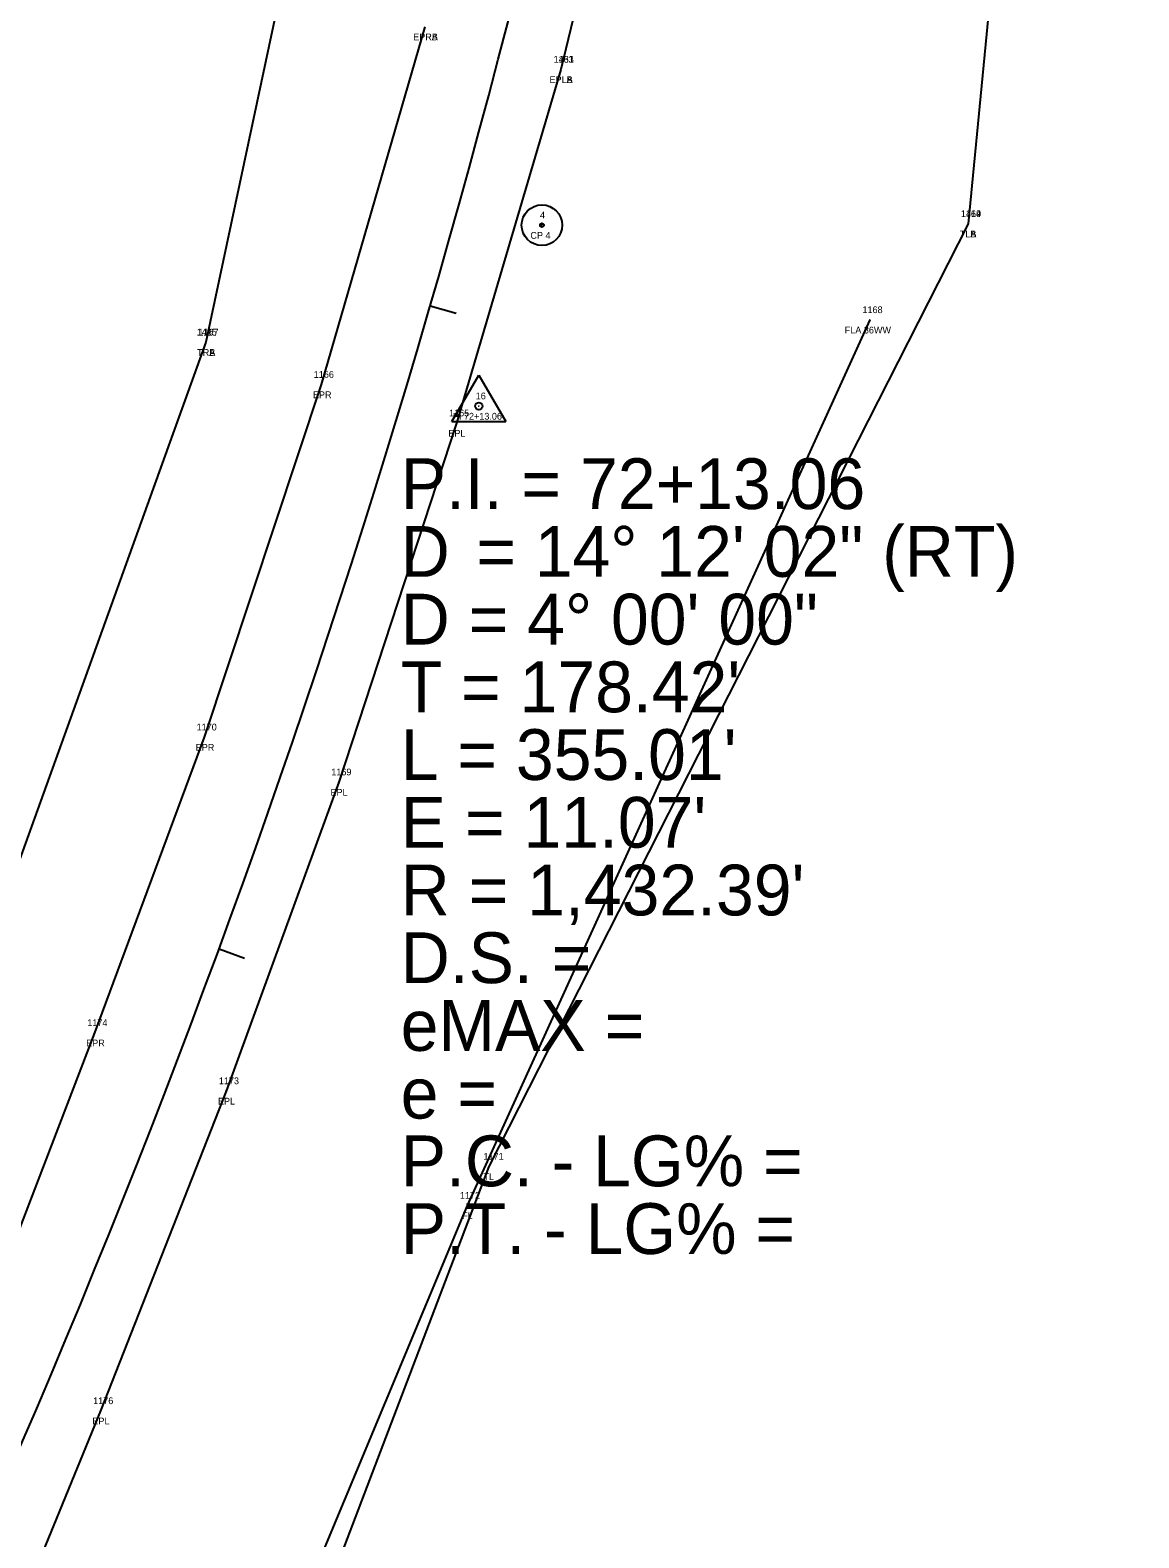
# Model space of a CAD drawing. Extents: x 2432632 to 2433497, y 684847 to 688233.
# Drawn here: x 2432999.3 to 2433163, y 685471.1 to 685693.7 of the extents above; entities that cross this region are included whole.
import ezdxf

# ---------------------------------------------------------------- set-up
doc = ezdxf.new("R2010")
doc.units = 0
for name, color, linetype in [('RD_EX_Fence_Other', 7, 'Continuous'), ('RD_EX_Fence_Other_txCode', 7, 'Continuous'), ('RD_EX_Road', 7, 'Continuous'), ('RD_EX_Road_txCode', 7, 'Continuous'), ('RD_EX_VEG', 7, 'Continuous'), ('RD_EX_VEG_txCode', 7, 'Continuous'), ('RD_HC_Cl', 7, 'Continuous'), ('RD_HC_Data', 7, 'Continuous'), ('RD_HC_Data_Tic', 7, 'Continuous'), ('RD_HC_txCode', 7, 'Continuous'), ('RD_SMD_Locator', 7, 'Continuous')]:
    doc.layers.add(name, color=color, linetype=linetype)

msp = doc.modelspace()

# ---------------------------------------------------------------- linework, layer by layer
at = {"layer": 'RD_EX_Fence_Other'}
msp.add_lwpolyline([(2433123.26, 685650.94), (2433063.8, 685520.15), (2433021.44, 685418.51), (2432949, 685234.28), (2432929.52, 685179.08)], dxfattribs=at)
at = {"layer": 'RD_EX_Road'}
for points in [[(2433142.75, 686017.3), (2433137.62, 685988.23), (2433129.83, 685944.15), (2433125.56, 685930.12), (2433108.96, 685832.94), (2433099.86, 685784.62), (2433089.82, 685738.23), (2433077.66, 685687.92)], [(2433057.55, 685694.23), (2433042.27, 685641.38), (2433024.96, 685589.31), (2433008.78, 685545.65), (2432989.83, 685496.35), (2432969.04, 685447.03), (2432957.98, 685420.84), (2432946.33, 685394.97), (2432928.47, 685353.31), (2432900.81, 685290.04), (2432890.58, 685267.74), (2432865.39, 685209.09), (2432858.68, 685194.25), (2432808.1, 685079.72), (2432767.11, 684987)], [(2433077.66, 685687.92), (2433062.23, 685635.7), (2433044.84, 685582.68), (2433028.22, 685537.07), (2433009.68, 685489.83), (2432988.53, 685438.27), (2432948.62, 685345.62), (2432907.86, 685252.74), (2432887.37, 685205.96), (2432872.08, 685170.45), (2432827.85, 685071.69), (2432787.31, 684979.59)]]:
    msp.add_lwpolyline(points, dxfattribs=at)
at = {"layer": 'RD_EX_VEG'}
msp.add_line((2433162.99, 685926.41), (2433137.8, 685665.13), dxfattribs=at)
for points in [[(2433091.33, 685944.6), (2433043.36, 685732.71), (2433025.22, 685647.63)], [(2433137.8, 685665.13), (2433067, 685525.91), (2432991.08, 685326.61), (2432934.15, 685190.44)], [(2433025.22, 685647.63), (2432992.1, 685555.75), (2432950.65, 685455.04), (2432854.18, 685219.34)]]:
    msp.add_lwpolyline(points, dxfattribs=at)
at = {"layer": 'RD_HC_Cl'}
msp.add_arc((2431682.72, 686052.2), 1432.39, 336.23293, 350.43349, dxfattribs=at)
at = {"layer": 'RD_HC_Data'}
for p, q in [((2433061.57, 685635.92), (2433065.54, 685642.8)), ((2433065.54, 685642.8), (2433069.51, 685635.92)), ((2433061.57, 685635.92), (2433069.51, 685635.92))]:
    msp.add_line(p, q, dxfattribs=at)
for centre, radius in [((2433074.85, 685664.92), 3), ((2433074.85, 685664.92), 0.282), ((2433065.54, 685638.21), 0.529)]:
    msp.add_circle(centre, radius, dxfattribs=at)
at = {"layer": 'RD_HC_Data_Tic'}
for p, q in [((2433058.37, 685653.04), (2433062.21, 685651.92)), ((2433027.18, 685558.05), (2433030.93, 685556.67))]:
    msp.add_line(p, q, dxfattribs=at)
at = {"layer": 'RD_SMD_Locator'}
for centre in [(2433077.66, 685687.92), (2433077.66, 685687.92), (2433074.85, 685664.92), (2433137.8, 685665.13), (2433137.8, 685665.13), (2433123.26, 685650.94), (2433025.22, 685647.63), (2433025.22, 685647.63), (2433042.27, 685641.38), (2433065.54, 685638.21), (2433062.23, 685635.7), (2433024.96, 685589.31), (2433044.84, 685582.68), (2433008.78, 685545.65), (2433028.22, 685537.07), (2433067, 685525.91), (2433063.8, 685520.15), (2433009.68, 685489.83)]:
    msp.add_circle(centre, 0.001, dxfattribs=at)

# ---------------------------------------------------------------- texts
at = {"layer": 'RD_EX_Fence_Other_txCode'}
for s, p in [('1168', (2433122.18, 685651.94)), ('FLA 36WW', (2433119.56, 685648.94)), ('1172', (2433062.74, 685521.15)), ('FL', (2433063.07, 685518.15))]:
    msp.add_text(s, height=1, dxfattribs=at).set_placement(p)
at = {"layer": 'RD_EX_Road_txCode'}
for s, p in [('EPRA', (2433055.83, 685692.23)), ('EPRB', (2433055.85, 685692.23)), ('1163', (2433076.57, 685688.92)), ('1431', (2433076.59, 685688.92)), ('EPLA', (2433075.96, 685685.92)), ('EPLB', (2433075.98, 685685.92)), ('1166', (2433041.16, 685642.38)), ('EPR', (2433041.04, 685639.38)), ('1165', (2433061.14, 685636.7)), ('EPL', (2433061.03, 685633.7)), ('1170', (2433023.86, 685590.31)), ('EPR', (2433023.73, 685587.31)), ('1169', (2433043.75, 685583.68)), ('EPL', (2433043.63, 685580.68)), ('1174', (2433007.72, 685546.65)), ('EPR', (2433007.56, 685543.65)), ('1173', (2433027.15, 685538.07)), ('EPL', (2433027.01, 685535.07)), ('1176', (2433008.59, 685490.83)), ('EPL', (2433008.47, 685487.83))]:
    msp.add_text(s, height=1, dxfattribs=at).set_placement(p)
at = {"layer": 'RD_EX_VEG_txCode'}
for s, p in [('1164', (2433136.71, 685666.13)), ('1419', (2433136.73, 685666.13)), ('TLA', (2433136.54, 685663.13)), ('TLB', (2433136.55, 685663.13)), ('1435', (2433023.87, 685648.63)), ('1167', (2433024.13, 685648.63)), ('TRA', (2433023.94, 685645.63)), ('TRB', (2433023.95, 685645.63)), ('1171', (2433066.22, 685526.91)), ('TL', (2433066.23, 685523.91))]:
    msp.add_text(s, height=1, dxfattribs=at).set_placement(p)
at = {"layer": 'RD_HC_Data'}
for s, p in [('P.I. = 72+13.06', (2433054, 685623)), ('D', (2433054, 685613)), ('    = 14%%d 12\' 02" (RT)', (2433054, 685613)), ('D = 4%%d 00\' 00"', (2433054, 685603)), ("T = 178.42'", (2433054, 685593)), ("L = 355.01'", (2433054, 685583)), ("E = 11.07'", (2433054, 685573)), ("R = 1,432.39'", (2433054, 685563)), ('D.S. = ', (2433054, 685553)), ('eMAX = ', (2433054, 685543)), ('e = ', (2433054, 685533)), ('P.C. - LG% = ', (2433054, 685523)), ('P.T. - LG% = ', (2433054, 685513))]:
    msp.add_text(s, height=7.5, dxfattribs=at).set_placement(p)
at = {"layer": 'RD_HC_txCode'}
for s, p in [('4', (2433074.56, 685665.92)), ('CP 4', (2433073.15, 685662.92)), ('16', (2433065.07, 685639.21)), ('PI 72+13.06', (2433061.7, 685636.21))]:
    msp.add_text(s, height=1, dxfattribs=at).set_placement(p)

doc.saveas('drawing.dxf')
